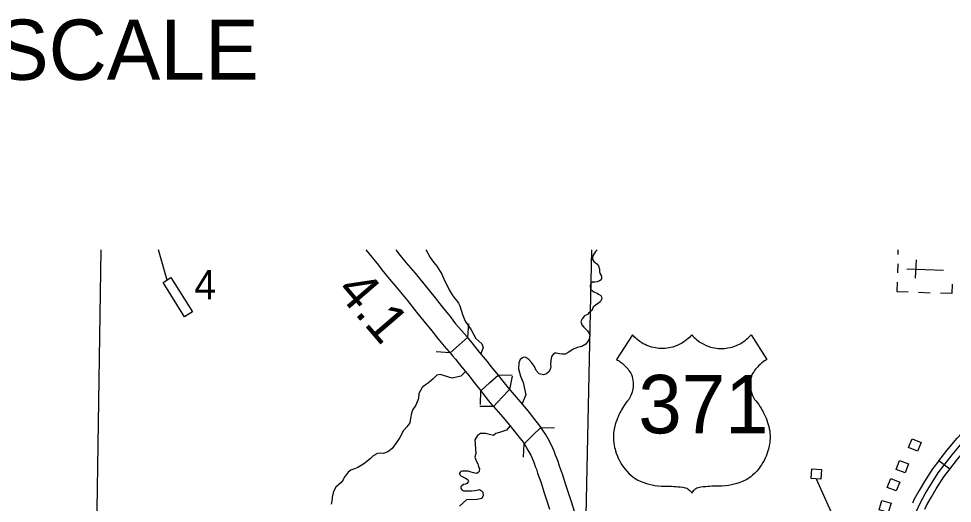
# Model space of a CAD drawing. Extents: x 61396 to 64680, y 55472 to 57605.
# Drawn here: x 62426.4 to 62743.1, y 56599.4 to 56763.6 of the extents above; entities that cross this region are included whole.
import ezdxf

# ---------------------------------------------------------------- set-up
doc = ezdxf.new("R2010")
doc.units = 0
for name, color, linetype in [('15', 7, 'Continuous'), ('22', 7, 'Continuous'), ('31', 7, 'Continuous'), ('35', 7, 'Continuous'), ('37', 7, 'Continuous'), ('48', 7, 'Continuous'), ('5', 7, 'Continuous'), ('56', 7, 'Continuous'), ('57', 7, 'Continuous'), ('Default', 7, 'Continuous')]:
    doc.layers.add(name, color=color, linetype=linetype)

msp = doc.modelspace()

# ---------------------------------------------------------------- linework, layer by layer
at = {"layer": '15'}
for points in [[(62578.67, 56655.56), (62575.69, 56652.98), (62572.76, 56650.43), (62572.45, 56650.84), (62570.86, 56652.7), (62568.57, 56655.33), (62566.7, 56657.82), (62563.98, 56661.07), (62561.53, 56664.21), (62558.27, 56668.26), (62554.89, 56672.35), (62551.79, 56676.02), (62549.73, 56678.5), (62548.55, 56680.06), (62545.41, 56683.94), (62544.29, 56685.27)], [(62554.38, 56685.27), (62554.71, 56684.87), (62555.85, 56683.35), (62557.77, 56681.04), (62560.88, 56677.36), (62564.33, 56673.2), (62567.66, 56669.05), (62570.05, 56665.98), (62572.82, 56662.68), (62574.65, 56660.24), (62576.78, 56657.8), (62578.51, 56655.77), (62578.67, 56655.56)], [(62578.67, 56655.56), (62579.65, 56654.3), (62580.57, 56653.22), (62582.67, 56650.62), (62585.31, 56647.47), (62586.61, 56645.77), (62589.02, 56642.82)], [(62572.76, 56650.43), (62573.58, 56649.37), (62574.56, 56648.23), (62576.64, 56645.66), (62579.21, 56642.59), (62580.47, 56640.93), (62583.24, 56637.55)], [(62583.24, 56637.55), (62586.26, 56640.3), (62589.02, 56642.82), (62589.76, 56641.91), (62591.98, 56639.11), (62592.94, 56637.96)], [(62592.94, 56637.96), (62590.47, 56635.36), (62587.53, 56632.26), (62587.06, 56632.81), (62585.91, 56634.18), (62583.67, 56637.02), (62583.24, 56637.55)], [(62592.94, 56637.96), (62593.01, 56637.87), (62596.64, 56633.68), (62599.13, 56630.7), (62601.84, 56627.29), (62603.49, 56625.14)], [(62587.53, 56632.26), (62590.69, 56628.61), (62593.08, 56625.76), (62595.68, 56622.49), (62597.5, 56620.11), (62597.85, 56619.58)], [(62614.94, 56596.58), (62613.93, 56599.87), (62612.77, 56603.27), (62612.16, 56605.33), (62610.86, 56609.28), (62609.85, 56611.99), (62609.43, 56613.52), (62608.92, 56614.71), (62608.55, 56615.75), (62608.01, 56617.1), (62607.14, 56619.1), (62605.99, 56621.25), (62605.07, 56622.83), (62603.87, 56624.64), (62603.49, 56625.14), (62600.57, 56622.31), (62597.85, 56619.58)], [(62597.85, 56619.58), (62598.43, 56618.7), (62599.17, 56617.43), (62600.1, 56615.69), (62600.8, 56614.08), (62601.25, 56612.98), (62601.64, 56611.88), (62602.04, 56610.94), (62602.42, 56609.57), (62603.49, 56606.69), (62604.71, 56603), (62605.33, 56600.9), (62606.5, 56597.47)]]:
    msp.add_lwpolyline(points, dxfattribs=at)
at = {"layer": '22'}
for points in [[(62654.73, 56656.48), (62654.32, 56656.01), (62653.93, 56655.61), (62653.48, 56655.19), (62653, 56654.78), (62652.53, 56654.42), (62651.97, 56654.02), (62651.36, 56653.65), (62650.67, 56653.27), (62649.8, 56652.86), (62649.12, 56652.6), (62648.37, 56652.35), (62647.67, 56652.17), (62647.03, 56652.04), (62646.36, 56651.94), (62645.74, 56651.87), (62644.88, 56651.83), (62644.19, 56651.84), (62643.59, 56651.88), (62643.02, 56651.94), (62642.44, 56652.03), (62641.71, 56652.18), (62641.04, 56652.35), (62640.21, 56652.62), (62639.52, 56652.89), (62638.88, 56653.18), (62638.3, 56653.49), (62637.77, 56653.8), (62637.17, 56654.2), (62636.62, 56654.6), (62636.15, 56654.98), (62635.75, 56655.34), (62635.34, 56655.73), (62634.95, 56656.15), (62634.62, 56656.52), (62629.21, 56648.16), (62629.6, 56647.93), (62630.06, 56647.63), (62630.5, 56647.32), (62631.08, 56646.86), (62631.54, 56646.46), (62631.95, 56646.08), (62632.37, 56645.65), (62632.8, 56645.18), (62633.11, 56644.81), (62633.41, 56644.41), (62633.72, 56643.98), (62634.02, 56643.53), (62634.3, 56643), (62634.51, 56642.35), (62634.66, 56641.7), (62634.78, 56641.01), (62634.85, 56640.37), (62634.87, 56639.75), (62634.86, 56639.17), (62634.82, 56638.71), (62634.74, 56638.14), (62634.63, 56637.6), (62634.49, 56637.02), (62634.32, 56636.51), (62634.1, 56635.94), (62633.75, 56635.2), (62633.39, 56634.62), (62632.95, 56634.1), (62632.42, 56633.42), (62631.99, 56632.83), (62631.59, 56632.23), (62631.22, 56631.65), (62630.91, 56631.12), (62630.64, 56630.63), (62630.34, 56630.05), (62630.01, 56629.36), (62629.72, 56628.7), (62629.51, 56628.2), (62629.28, 56627.56), (62629.01, 56626.78), (62628.8, 56626.14), (62628.61, 56625.43), (62628.42, 56624.61), (62628.3, 56623.88), (62628.22, 56623.12), (62628.17, 56622.28), (62628.16, 56621.5), (62628.2, 56620.74), (62628.29, 56619.84), (62628.43, 56618.99), (62628.57, 56618.35), (62628.72, 56617.78), (62628.9, 56617.14), (62629.15, 56616.35), (62629.51, 56615.39), (62629.82, 56614.68), (62630.17, 56613.95), (62630.57, 56613.23), (62631.07, 56612.41), (62631.6, 56611.65), (62632.11, 56611), (62632.69, 56610.32), (62633.44, 56609.55), (62634.07, 56608.96), (62634.73, 56608.41)], [(62654.73, 56656.48), (62655.14, 56656.01), (62655.53, 56655.61), (62655.98, 56655.19), (62656.46, 56654.78), (62656.93, 56654.42), (62657.49, 56654.02), (62658.1, 56653.65), (62658.79, 56653.27), (62659.66, 56652.86), (62660.33, 56652.6), (62661.09, 56652.35), (62661.79, 56652.17), (62662.43, 56652.04), (62663.1, 56651.94), (62663.72, 56651.87), (62664.58, 56651.83), (62665.27, 56651.84), (62665.87, 56651.88), (62666.44, 56651.94), (62667.02, 56652.03), (62667.75, 56652.18), (62668.42, 56652.35), (62669.25, 56652.62), (62669.94, 56652.89), (62670.58, 56653.18), (62671.16, 56653.49), (62671.69, 56653.8), (62672.29, 56654.2), (62672.84, 56654.6), (62673.31, 56654.98), (62673.71, 56655.34), (62674.12, 56655.73), (62674.51, 56656.15), (62674.84, 56656.52), (62680.25, 56648.16), (62679.86, 56647.93), (62679.4, 56647.63), (62678.96, 56647.32), (62678.38, 56646.86), (62677.92, 56646.46), (62677.51, 56646.08), (62677.09, 56645.65), (62676.66, 56645.18), (62676.35, 56644.81), (62676.05, 56644.41), (62675.74, 56643.98), (62675.44, 56643.53), (62675.16, 56643), (62674.95, 56642.35), (62674.79, 56641.7), (62674.68, 56641.01), (62674.61, 56640.37), (62674.59, 56639.75), (62674.6, 56639.17), (62674.64, 56638.71), (62674.72, 56638.14), (62674.82, 56637.6), (62674.97, 56637.02), (62675.14, 56636.51), (62675.36, 56635.94), (62675.71, 56635.2), (62676.07, 56634.62), (62676.51, 56634.1), (62677.04, 56633.42), (62677.47, 56632.83), (62677.87, 56632.23), (62678.24, 56631.65), (62678.55, 56631.12), (62678.82, 56630.63), (62679.12, 56630.05), (62679.45, 56629.36), (62679.74, 56628.7), (62679.95, 56628.2), (62680.18, 56627.56), (62680.45, 56626.78), (62680.66, 56626.14), (62680.85, 56625.43), (62681.03, 56624.61), (62681.16, 56623.88), (62681.24, 56623.12), (62681.29, 56622.28), (62681.3, 56621.5), (62681.26, 56620.74), (62681.17, 56619.84), (62681.03, 56618.99), (62680.89, 56618.35), (62680.74, 56617.78), (62680.56, 56617.14), (62680.31, 56616.35), (62679.95, 56615.39), (62679.64, 56614.68), (62679.29, 56613.95), (62678.89, 56613.23), (62678.38, 56612.41), (62677.86, 56611.65), (62677.35, 56611), (62676.77, 56610.32), (62676.02, 56609.55), (62675.39, 56608.96), (62674.73, 56608.41)], [(62634.73, 56608.41), (62635.4, 56607.9), (62636.22, 56607.37), (62637.24, 56606.91), (62638.44, 56606.45), (62639.42, 56606.13), (62640.3, 56605.89), (62641.29, 56605.66), (62642.22, 56605.49), (62643.23, 56605.35), (62644.49, 56605.24), (62645.46, 56605.21), (62646.29, 56605.21), (62647.09, 56605.2), (62647.9, 56605.18), (62648.66, 56605.14), (62649.33, 56605.09), (62649.99, 56605.04), (62650.83, 56604.95), (62651.65, 56604.85), (62652.14, 56604.78), (62652.55, 56604.7), (62653.04, 56604.5), (62653.32, 56604.34), (62653.57, 56604.18), (62653.91, 56603.91), (62654.23, 56603.58), (62654.49, 56603.24), (62654.73, 56602.85)], [(62674.73, 56608.41), (62674.06, 56607.9), (62673.24, 56607.37), (62672.22, 56606.91), (62671.02, 56606.45), (62670.04, 56606.13), (62669.16, 56605.89), (62668.17, 56605.66), (62667.23, 56605.49), (62666.23, 56605.35), (62664.97, 56605.24), (62664, 56605.21), (62663.17, 56605.21), (62662.37, 56605.2), (62661.56, 56605.18), (62660.8, 56605.14), (62660.13, 56605.09), (62659.47, 56605.04), (62658.63, 56604.95), (62657.81, 56604.85), (62657.32, 56604.78), (62656.91, 56604.7), (62656.42, 56604.5), (62656.14, 56604.34), (62655.89, 56604.18), (62655.55, 56603.91), (62655.23, 56603.58), (62654.97, 56603.24), (62654.73, 56602.85)]]:
    msp.add_lwpolyline(points, dxfattribs=at)
at = {"layer": '31'}
msp.add_line((62742.26, 56610.95), (62738.56, 56613.83), dxfattribs=at)
for points in [[(62738.56, 56613.83), (62741.24, 56617.26), (62744.72, 56621.43), (62747.9, 56624.81), (62749.28, 56626.47)], [(62742.26, 56610.95), (62744.89, 56614.31), (62748.23, 56618.33), (62751.41, 56621.7), (62752.88, 56623.47)], [(62724.12, 56583.83), (62724.85, 56584.76), (62725.89, 56586.19), (62726.71, 56587.55), (62729.67, 56593.87), (62730.81, 56596.5), (62732.3, 56599.72), (62733.94, 56602.57), (62735.67, 56605.58), (62738.32, 56609.72), (62743.06, 56615.78), (62746.48, 56619.88)], [(62738.56, 56613.83), (62736.41, 56611.07), (62733.67, 56606.8), (62731.91, 56603.74), (62730.21, 56600.8), (62729.57, 56599.41)], [(62733.82, 56597.44), (62734.38, 56598.64), (62735.97, 56601.4), (62737.67, 56604.36), (62740.24, 56608.36), (62742.26, 56610.95)]]:
    msp.add_lwpolyline(points, dxfattribs=at)
at = {"layer": '35'}
for points in [[(62564.55, 56685.27), (62564.73, 56684.91), (62566.03, 56682.69), (62567.11, 56681.1), (62568.28, 56679.74), (62569.93, 56677.09), (62570.8, 56675.12), (62571.56, 56673.62), (62572.46, 56671.78), (62573.41, 56670.09), (62574.36, 56668.75), (62575.15, 56667.88), (62575.63, 56667.26), (62576.08, 56666.35), (62576.95, 56663.38), (62577.85, 56661.1), (62579.88, 56658.15), (62581.47, 56655.29), (62583.54, 56653.45), (62583.94, 56652.18), (62583.23, 56650.1)], [(62622.6, 56685.27), (62622.11, 56684.67), (62621.21, 56683.25), (62621.09, 56682.69), (62621.06, 56682.4), (62621.1, 56681.96), (62621.54, 56681.37), (62621.92, 56680.97), (62622.55, 56680.57), (62623.15, 56679.85), (62623.41, 56678.79), (62623.48, 56677.88), (62623.68, 56677.1), (62623.97, 56676.6), (62624.16, 56676.03), (62624.13, 56675.37), (62623.98, 56675.12), (62623.48, 56674.74), (62622.7, 56674.45), (62621.86, 56674.38), (62621.08, 56674.31), (62620.49, 56673.89), (62620.24, 56673.14), (62620.41, 56672.01), (62621.51, 56671.08), (62622.68, 56670.59), (62623.15, 56670.31), (62623.87, 56669.85), (62624.13, 56669.38), (62624.2, 56668.63), (62623.8, 56667.78), (62622.96, 56667.14), (62622.06, 56666.56), (62621.31, 56665.83), (62620.79, 56664.7), (62619.74, 56663.81), (62619.33, 56663.4), (62618.34, 56662.88), (62617.53, 56661.93), (62617.16, 56661.05), (62617.17, 56660.64), (62617.42, 56659.92), (62618.09, 56659.11), (62619.32, 56657.84), (62619.77, 56657.22), (62620.21, 56656.41), (62620.1, 56655.4), (62619.6, 56654.49), (62618.8, 56653.28), (62617.49, 56652.52), (62615.96, 56652.16), (62614.53, 56651.58), (62613.75, 56651.07), (62612.82, 56650.52), (62611.85, 56649.98), (62610.76, 56649.97), (62609.82, 56650.08), (62608.78, 56650.23), (62608.31, 56650.22), (62607.6, 56649.71), (62607.16, 56649.17), (62606.93, 56647.67), (62606.85, 56646.38), (62606.88, 56645.72), (62606.74, 56644.78), (62606.31, 56643.99), (62605.5, 56643.22), (62604.41, 56642.96), (62603.03, 56643.32), (62601.95, 56644.44), (62601.37, 56645.79), (62600.39, 56647.16), (62599.44, 56648.12), (62598.43, 56648.77), (62597.75, 56648.89), (62597.31, 56648.72), (62596.53, 56648.15), (62596.04, 56646.98), (62596, 56644.94), (62596.68, 56642.44), (62597.51, 56640.38), (62598.43, 56636.13), (62597.26, 56633.21)], [(62577.99, 56644.03), (62576.37, 56642.45), (62573.41, 56641.82), (62569.44, 56643.09), (62568.25, 56642.79), (62566.98, 56641.59), (62565.49, 56640.22), (62564.47, 56639.52), (62563.31, 56638.66), (62562.21, 56636.61), (62562.1, 56634.91), (62561.18, 56632.64), (62560.07, 56631.19), (62559.64, 56629.96), (62559.31, 56628.14), (62559.08, 56626.63), (62558.06, 56625.33), (62557, 56624.03), (62555.68, 56621.69), (62554.6, 56619.99), (62553.12, 56617.96), (62551.63, 56616.85), (62550.19, 56616.33), (62549, 56616.35), (62548.09, 56616.28), (62546.72, 56615.48), (62545.61, 56614.46), (62543.49, 56612.81), (62542.65, 56612.27), (62541.47, 56611.59), (62540.32, 56611.11), (62539.07, 56610.6), (62538.2, 56609.9), (62537.12, 56608.6), (62536.9, 56608.34), (62536.53, 56607.4), (62535.85, 56606.48), (62534.95, 56605.72), (62533.96, 56604.92), (62533.28, 56603.6), (62532.95, 56602.46), (62532.71, 56601.46), (62532.69, 56600.11), (62532.42, 56599.13)], [(62591.87, 56624.22), (62589.47, 56623.39), (62588.33, 56623.08), (62587.44, 56622.42), (62584.79, 56623.02), (62583.07, 56623.02), (62582.02, 56622.36), (62581.14, 56620.87), (62581.46, 56616.32), (62581.16, 56615.06), (62581.61, 56613.81), (62582.12, 56612.75), (62582.44, 56611.88), (62582.73, 56611.03), (62582.61, 56610.21), (62582.34, 56609.8), (62581.81, 56609.55), (62580.74, 56609.75), (62579.96, 56610), (62578.92, 56610.27), (62578.29, 56610.29), (62577.73, 56610.35), (62577.14, 56610.34), (62576.73, 56610.28), (62576.45, 56610.21), (62576.2, 56609.99), (62575.98, 56609.58), (62575.99, 56609.45), (62576.21, 56608.89), (62576.4, 56608.7), (62576.81, 56608.46), (62577.5, 56608.12), (62578.04, 56607.87), (62578.51, 56607.63), (62578.92, 56607.22), (62578.98, 56606.94), (62578.89, 56606.63), (62578.46, 56606.09), (62577.96, 56605.86), (62577.34, 56605.76), (62576.65, 56605.25), (62576.4, 56604.97), (62576.41, 56604.59), (62576.5, 56604.28), (62576.82, 56603.81), (62577.29, 56603.63), (62578.8, 56603.58), (62580.08, 56603.63), (62581.11, 56603.76), (62581.89, 56603.9), (62582.77, 56604.03), (62583.08, 56603.88), (62583.37, 56603.66), (62583.86, 56603.18), (62583.94, 56602.02), (62583.49, 56601.05), (62581.92, 56600.71), (62578.29, 56600.6), (62575.97, 56598.39)], [(62593.16, 56625.6), (62591.87, 56624.22)]]:
    msp.add_lwpolyline(points, dxfattribs=at)
at = {"layer": '37'}
for points in [[(62579.03, 56660.21), (62578.67, 56655.56)], [(62572.76, 56650.43), (62568.09, 56650.78)], [(62589.02, 56642.82), (62593.83, 56642.9)], [(62593.87, 56642.47), (62592.94, 56637.96)], [(62583.04, 56632.86), (62583.24, 56637.55)], [(62587.53, 56632.26), (62582.89, 56632.15)], [(62603.49, 56625.14), (62608.17, 56625.02)], [(62597.71, 56615.06), (62597.85, 56619.58)]]:
    msp.add_lwpolyline(points, dxfattribs=at)
at = {"layer": '5'}
for points in [[(62454.35, 56685.27), (62451.98, 56538.52)], [(62620.68, 56685.27), (62618.63, 56584.77)]]:
    msp.add_lwpolyline(points, dxfattribs=at)
at = {"layer": '56'}
for points in [[(62476.77, 56675.03), (62473.81, 56685.27)], [(62696.88, 56607.72), (62705.39, 56588.8)]]:
    msp.add_lwpolyline(points, dxfattribs=at)
for points in [[(62475.44, 56674.2), (62478.09, 56675.86), (62485.34, 56664.27), (62482.69, 56662.61)], [(62728.29, 56618.28), (62729.53, 56621.29), (62732.54, 56620.05), (62731.31, 56617.04)], [(62695.26, 56607.85), (62695.51, 56611.09), (62698.76, 56610.84), (62698.51, 56607.6)], [(62724.06, 56610.9), (62725.19, 56613.95), (62728.25, 56612.81), (62727.11, 56609.76)], [(62721.07, 56604.77), (62722.25, 56607.8), (62725.29, 56606.61), (62724.11, 56603.58)], [(62718.28, 56597.22), (62719.22, 56600.33), (62722.34, 56599.4), (62721.41, 56596.28)]]:
    msp.add_lwpolyline(points, close=True, dxfattribs=at)
at = {"layer": '57'}
for p, q in [((62730.67, 56675.64), (62730.92, 56681.92)), ((62724.61, 56680.59), (62724.49, 56677.47)), ((62727.67, 56678.89), (62740.16, 56678.4)), ((62733.92, 56678.65), (62733.92, 56678.65)), ((62733.92, 56678.65), (62733.92, 56678.65)), ((62731.69, 56670.91), (62735.59, 56670.76))]:
    msp.add_line(p, q, dxfattribs=at)
for points in [[(62724.73, 56683.69), (62724.79, 56685.27)], [(62724.37, 56674.33), (62724.25, 56671.2), (62728.15, 56671.05)], [(62743.1, 56673.6), (62742.98, 56670.47), (62739.08, 56670.63)]]:
    msp.add_lwpolyline(points, dxfattribs=at)

# ---------------------------------------------------------------- texts
at = {"layer": '22'}
msp.add_text('371', height=19.8, dxfattribs=at).set_placement((62636.61, 56623.1))
at = {"layer": '48'}
msp.add_text('4.1', height=13.2, rotation=310.6058, dxfattribs=at).set_placement((62533.72, 56671.2))
at = {"layer": '56'}
msp.add_text('4', height=9.9, dxfattribs=at).set_placement((62486.02, 56668.56))
at = {"layer": 'Default'}
msp.add_text('NOT TO SCALE', height=20.4, dxfattribs=at).set_placement((62307.79, 56742.9))

doc.saveas('drawing.dxf')
